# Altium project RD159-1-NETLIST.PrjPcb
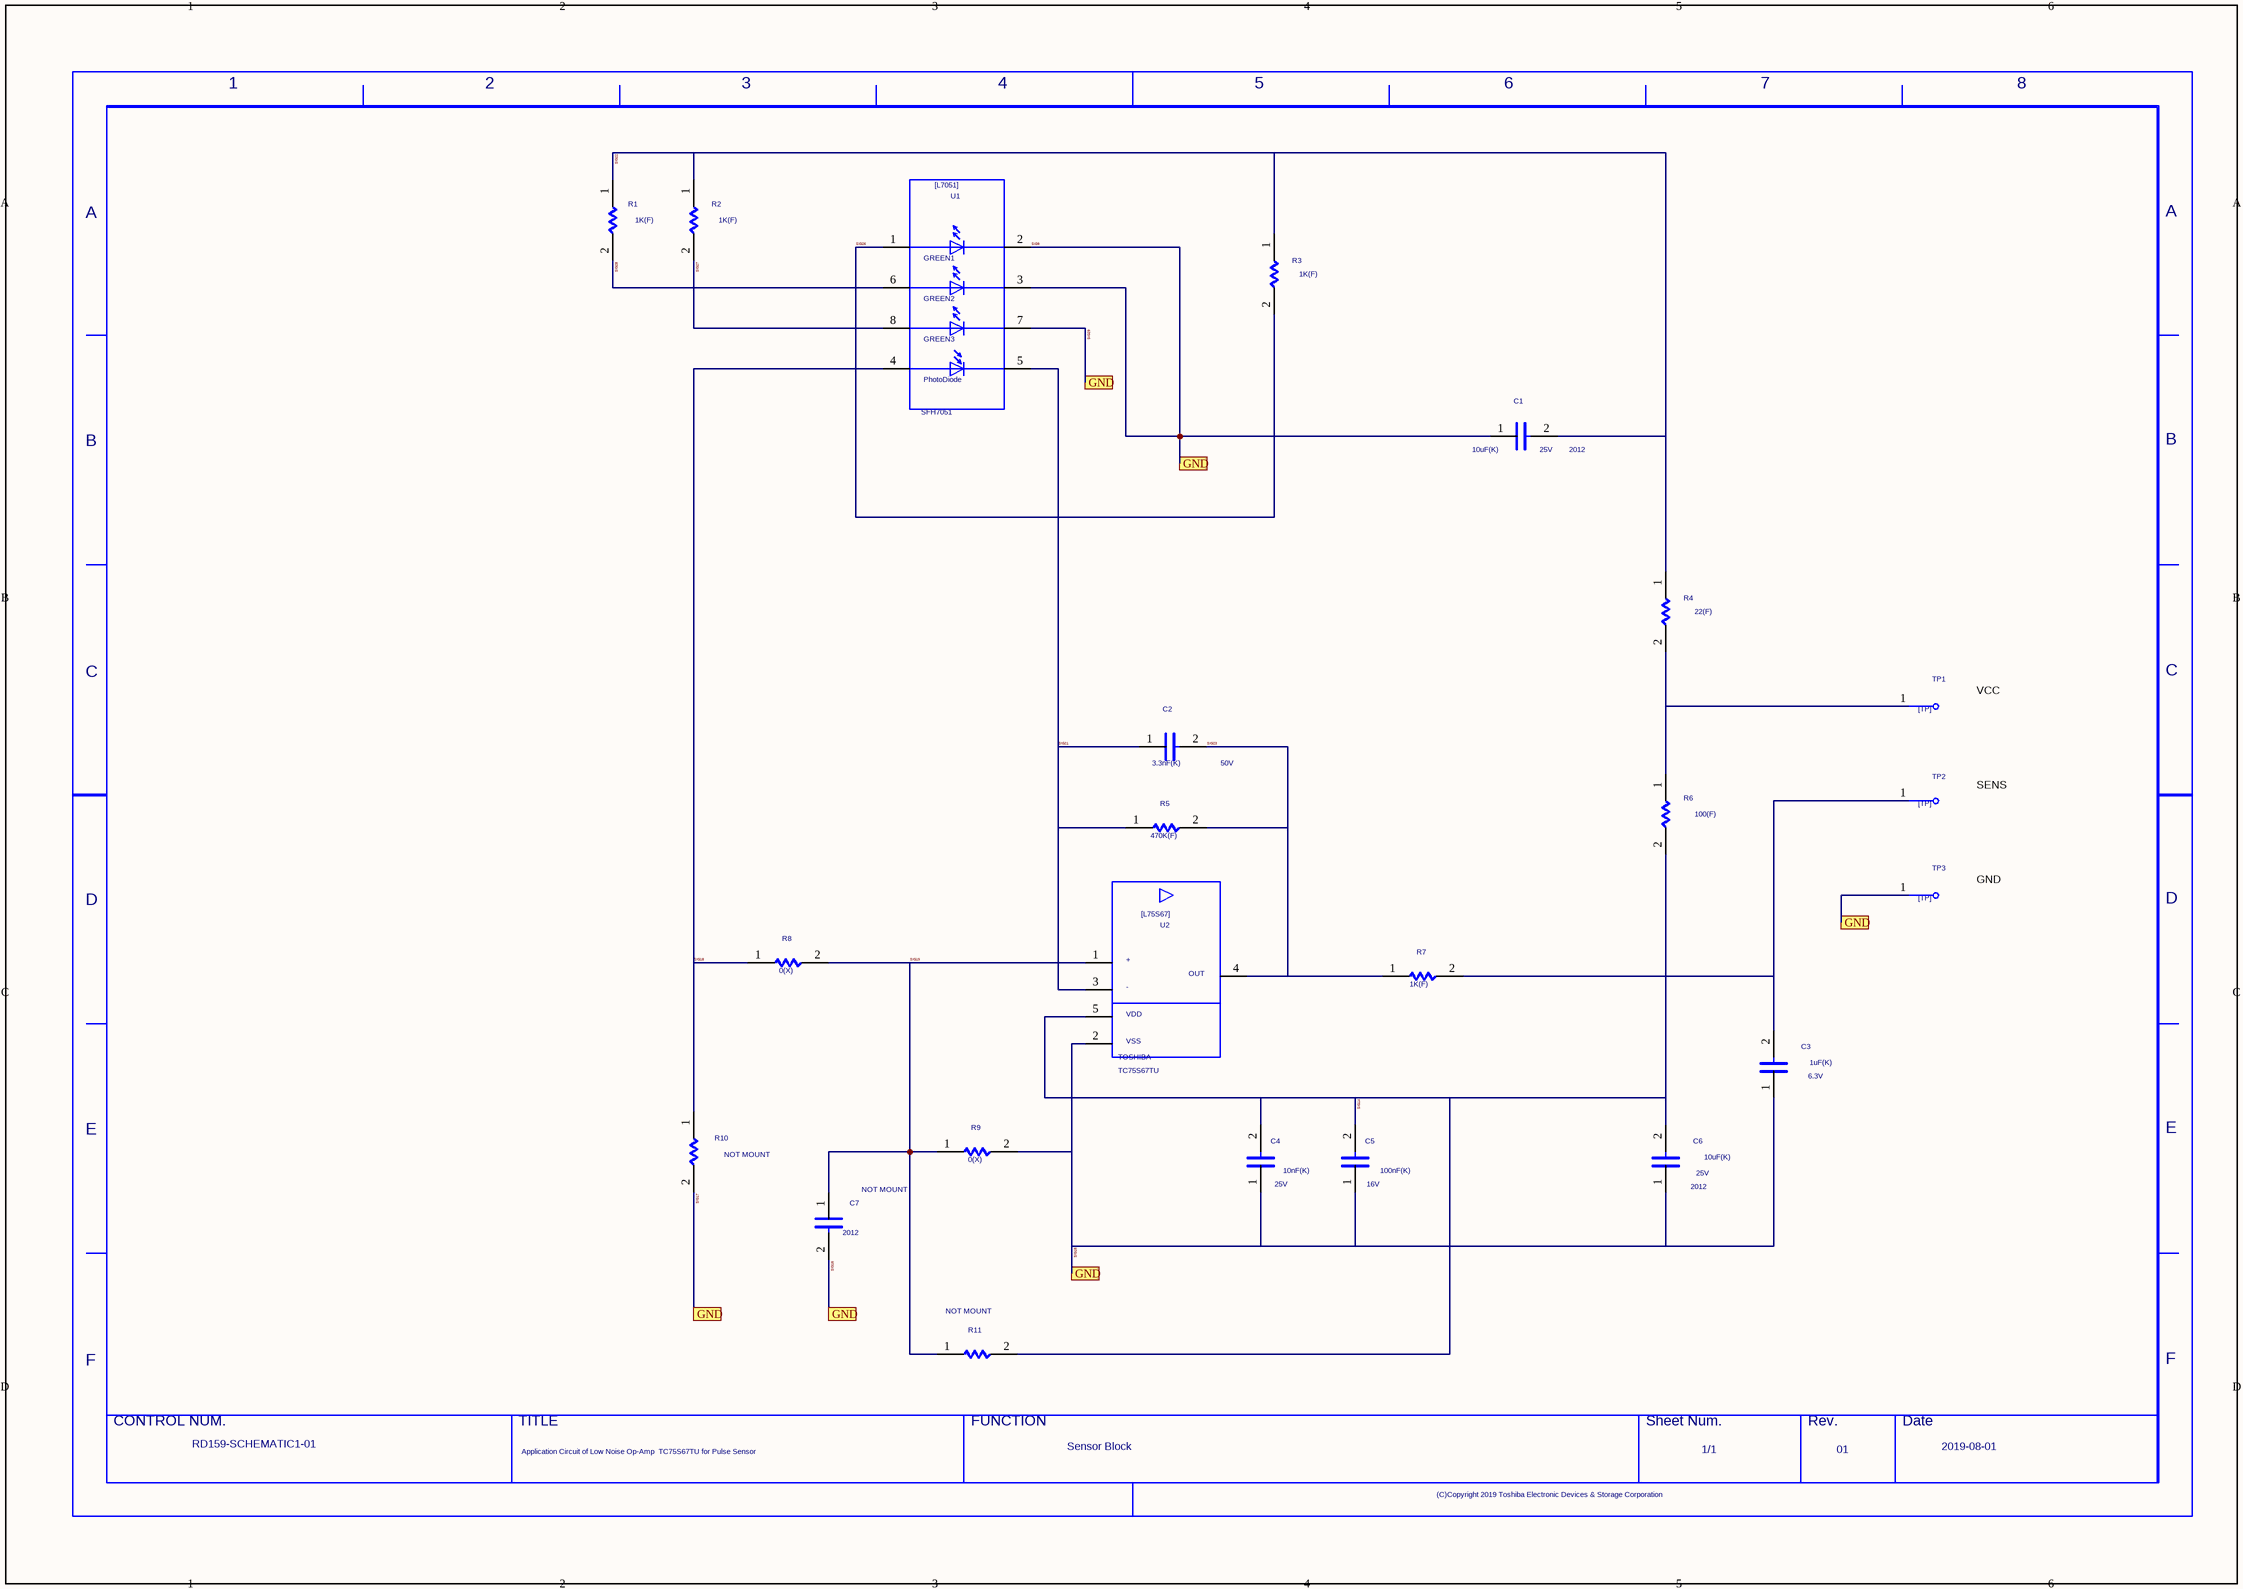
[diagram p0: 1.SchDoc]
1 sheet, 24 parts. Net scope: flat (ports and power ports of the same name join across sheets).

## Sheet 1.SchDoc
size 420 x 297 mm

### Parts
C1  SIZECODESMD: 2012  VAL2: 25V  VAL1: 10uF(K)  (hidden comment: C)
C2  VAL2: 50V  VAL1: 3.3nF(K)  (hidden comment: C)
C3  VAL2: 6.3V  VAL1: 1uF(K)  (hidden comment: C)
C4  VAL2: 25V  VAL1: 10nF(K)  (hidden comment: C)
C5  VAL2: 16V  VAL1: 100nF(K)  (hidden comment: C)
C6  SIZECODESMD: 2012  VAL2: 25V  VAL1: 10uF(K)  (hidden comment: C)
C7  NOTMOUNT: NOT MOUNT  SIZECODESMD: 2012  (hidden comment: C)
R1  VAL1: 1K(F)  (hidden comment: R)
R2  VAL1: 1K(F)  (hidden comment: R)
R3  VAL1: 1K(F)  (hidden comment: R)
R4  VAL1: 22(F)  (hidden comment: R)
R5  VAL1: 470K(F)  (hidden comment: R)
R6  VAL1: 100(F)  (hidden comment: R)
R7  VAL1: 1K(F)  (hidden comment: R)
R8  VAL1: 0(X)  (hidden comment: R)
R9  VAL1: 0(X)  (hidden comment: R)
R10  NOTMOUNT: NOT MOUNT  (hidden comment: R)
R11  NOTMOUNT: NOT MOUNT  (hidden comment: R)
TP1  TP  (value not drawn)
TP2  TP  (value not drawn)
TP3  TP  (value not drawn)
U1  VAL3: SFH7051  (hidden comment: L7051)
U2  USERCOMPTEXT3: TOSHIBA  VAL3: TC75S67TU  (hidden comment: L75S67)
U?  DATE: 2019-08-01  REVISION: 01  SHEETNUMBER: 1/1  FUNCTION: Sensor Block  TITLE: Application Circuit of Low Noise Op-Amp / TC75S67TU for Pulse Sensor  DRAWINGNUMBER: RD159-SCHEMATIC1-01  (hidden comment: WAKU_DEF100)

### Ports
GND

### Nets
SENS: C3.2 R7.2 TP2.1
SIG14: C4.2 C5.2 C6.2 R6.2 R11.2 U2.5
SIG15: C1.1 C3.1 C4.1 C5.1 C6.1 C7.2 R9.2 R10.2 TP3.1 U1.2 U1.3 U1.7 U2.2 ; port GND  [also labelled SIG16, SIG17, SIG29, SIG9]
SIG18: R8.1 R10.1 U1.4
SIG19: C7.1 R8.2 R9.1 R11.1 U2.1
SIG21: C2.1 R5.1 U1.5 U2.3
SIG22: C1.2 R1.1 R2.1 R3.1 R4.1
SIG23: C2.2 R5.2 R7.1 U2.4
SIG26: R3.2 U1.1
SIG27: R2.2 U1.8
SIG28: R1.2 U1.6
VCC: R4.2 R6.1 TP1.1

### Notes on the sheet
- VCC
- SENS
- GND

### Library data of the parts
C1 C6 = C: PARTNAME: GDM030002136; OriginalSymbolOrigin: (2540,7620); COMPONENTNAME: GDM030002136_package; MAXGCOUNT: 1
C2 = C: PARTNAME: G36030133418; OriginalSymbolOrigin: (2540,7620); COMPONENTNAME: G36030133418_package; MAXGCOUNT: 1; SIZECODESMD: 1005
C3 = C: PARTNAME: GDM030000207; OriginalSymbolOrigin: (2540,7620); COMPONENTNAME: GDM030000207_package; MAXGCOUNT: 1; SIZECODESMD: 1005
C4 = C: PARTNAME: GDM030002097; OriginalSymbolOrigin: (2540,7620); COMPONENTNAME: GDM030002097_package; MAXGCOUNT: 1; SIZECODESMD: 1005
C5 = C: PARTNAME: GDM030002515; OriginalSymbolOrigin: (2540,7620); COMPONENTNAME: GDM030002515_package; MAXGCOUNT: 1; SIZECODESMD: 1005
C7 = C: PARTNAME: GDM030000019; OriginalSymbolOrigin: (2540,7620); COMPONENTNAME: GDM030000019_package; MAXGCOUNT: 1
R1-R3 R7 = R: PARTNAME: GDM010001350; OriginalSymbolOrigin: (5080,5080); MAXGCOUNT: 1; COMPONENTNAME: GDM010001350_package; SIZECODESMD: 1005; VAL2: 100mW
R4 = R: PARTNAME: GDM010003904; OriginalSymbolOrigin: (5080,5080); MAXGCOUNT: 1; COMPONENTNAME: GDM010003904_package; SIZECODESMD: 1005; VAL2: 100mW
R5 = R: PARTNAME: G36010118169; OriginalSymbolOrigin: (5080,5080); MAXGCOUNT: 1; COMPONENTNAME: G36010118169_package; SIZECODESMD: 1005; VAL2: 100mW
R6 = R: PARTNAME: G36010118534; OriginalSymbolOrigin: (5080,5080); MAXGCOUNT: 1; COMPONENTNAME: G36010118534_package; SIZECODESMD: 1005; VAL2: 100mW
R8 R9 = R: PARTNAME: GDM010003025; OriginalSymbolOrigin: (5080,5080); MAXGCOUNT: 1; COMPONENTNAME: GDM010003025_package; SIZECODESMD: 1005; VAL2: 1A
R10 = R: PARTNAME: GDM010003025; OriginalSymbolOrigin: (5080,5080); MAXGCOUNT: 1; COMPONENTNAME: GDM010003025_package; SIZECODESMD: 1005
R11 = R: PARTNAME: GDM010002207; OriginalSymbolOrigin: (5080,5080); COMPONENTNAME: GDM010002207_package; MAXGCOUNT: 1; SIZECODESMD: 1005
TP1-TP3 = TP: TIME: 16:12:21; UPDATEUSER: fukuda-y; UPDATETIME: 16:18:11; SAVECOUNT: 2; SAVEAREA0: -242,-92,12810,7836; OriginalSymbolOrigin: (0,7620); FUNCTION: DCK7F1; COMPONENTNAME: DCK7F1_package; MAXGCOUNT: 1
U1 = L7051: PARTNAME: K47S002B; OUMEPARTTYPE: IC; TIME: 14:34:58; UPDATEUSER: w90028dm; UPDATETIME: 07:55:05; SAVECOUNT: 22; SAVEAREA0: -60238,-12931,88393,61056; OriginalSymbolOrigin: (5080,45720); COMPONENTNAME: K47S002B_package; MAXGCOUNT: 1
U2 = L75S67: PARTNAME: K47S002A; OUMEPARTTYPE: IC; TIME: 16:27:13; UPDATEUSER: 19990028; UPDATETIME: 13:02:06; SAVECOUNT: 13; SAVEAREA0: -72307,-25685,103712,61936; OriginalSymbolOrigin: (5080,35560); COMPONENTNAME: K47S002A_package; MAXGCOUNT: 1
U? = WAKU_DEF100: PLOTTIME: HH:MM; SAVEAREA0: 198008,-65938,436964,90161; TIME: 14:30:25; UPDATEUSER: cae; UPDATETIME: 13:18:10; SAVECOUNT: 4; OriginalSymbolOrigin: (10160,284480)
